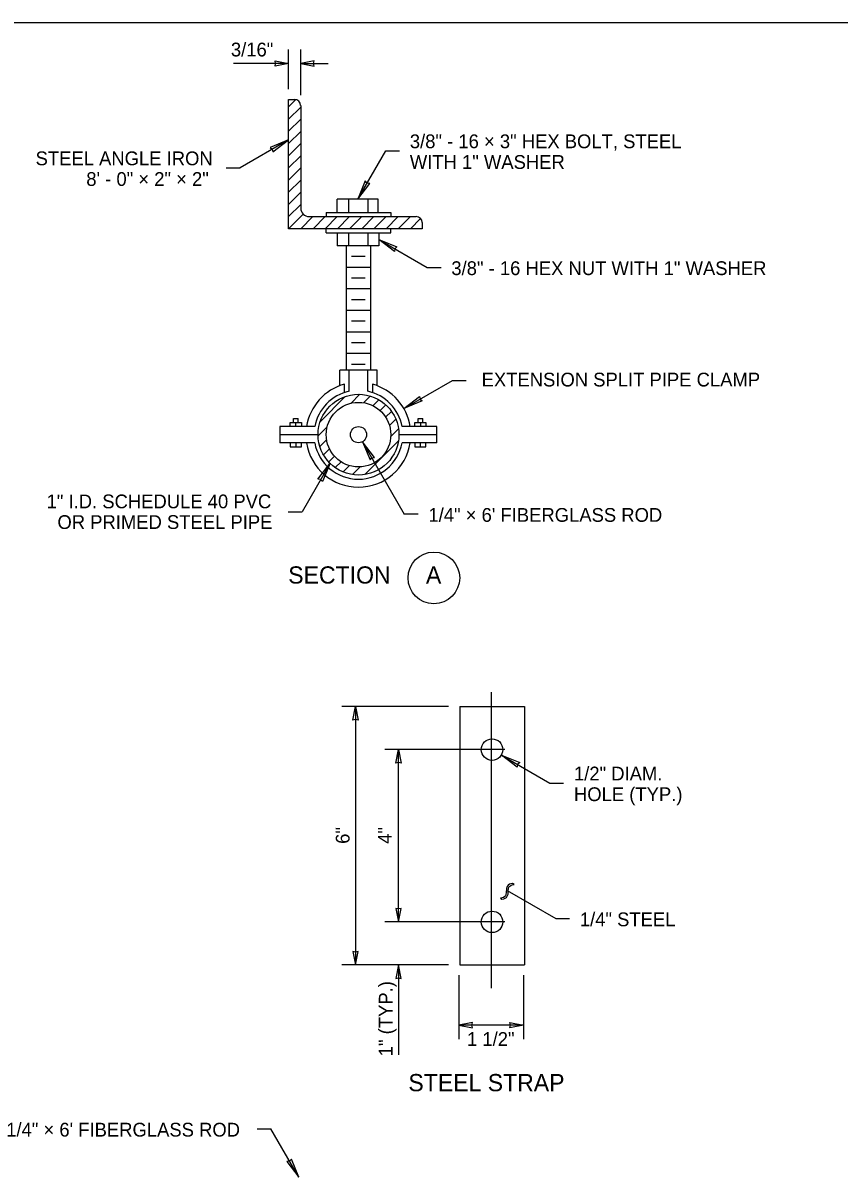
# Model space of a CAD drawing. Extents: x 99862 to 103151, y 100000 to 102076.
# Drawn here: x 100664 to 101611, y 100744 to 102076 of the extents above; entities that cross this region are included whole.
import ezdxf

# ---------------------------------------------------------------- set-up
doc = ezdxf.new("R2010")
doc.units = 0
for name, color, linetype in [('Level 1', 7, 'Continuous'), ('Level 13', 7, 'Continuous'), ('Level 15', 7, 'Continuous'), ('Level 20', 7, 'Continuous'), ('Level 3', 7, 'Continuous'), ('Level 4', 7, 'Continuous'), ('Level 6', 7, 'Continuous'), ('Level 8', 7, 'Continuous'), ('Level 9', 7, 'Continuous')]:
    doc.layers.add(name, color=color, linetype=linetype)

msp = doc.modelspace()

# ---------------------------------------------------------------- linework, layer by layer
at = {"layer": 'Level 1'}
for p, q in [((101223.3, 101232), (101083.8, 101232)), ((101223.3, 101032), (101083.8, 101032))]:
    msp.add_line(p, q, dxfattribs=at)
msp.add_lwpolyline([(99862, 99999.5), (103151, 99999.5), (103151, 102075.5), (99862, 102075.5)], close=True, dxfattribs=at)
at = {"layer": 'Level 13'}
for p, q in [((101028.5, 101855.6), (101028.5, 101870.8)), ((101076.1, 101870.8), (101028.5, 101870.8)), ((101041.7, 101870.8), (101041.7, 101855.4)), ((101063.9, 101870.8), (101063.9, 101855.4)), ((101076.1, 101855.6), (101076.1, 101870.8)), ((101015.6, 101855.4), (101090.6, 101855.4)), ((101015.6, 101855.4), (101015.6, 101850.7)), ((101090.6, 101855.4), (101090.6, 101850.7)), ((101015.6, 101831.9), (101015.6, 101836.6)), ((101015.6, 101831.9), (101090.6, 101831.9)), ((101028.5, 101831.9), (101028.5, 101816.7)), ((101041.7, 101831.9), (101041.7, 101816.7)), ((101063.9, 101831.9), (101063.9, 101816.7)), ((101076.7, 101831.9), (101076.7, 101816.7)), ((101090.6, 101831.9), (101090.6, 101836.6)), ((101076.7, 101816.7), (101028.5, 101816.7)), ((101039, 101816.7), (101039, 101672.5)), ((101067.1, 101816.7), (101067.1, 101672.5)), ((101061.1, 101804.2), (101045, 101804.2)), ((101061.1, 101804.2), (101045, 101804.2)), ((101061.1, 101804.2), (101045, 101804.2)), ((101061.1, 101804.2), (101045, 101804.2)), ((101061.1, 101804.2), (101045, 101804.2)), ((101061.1, 101804.2), (101045, 101804.2)), ((101061.1, 101804.2), (101045, 101804.2)), ((101061.1, 101804.2), (101045, 101804.2)), ((101061.1, 101804.2), (101045, 101804.2)), ((101061.1, 101804.2), (101045, 101804.2)), ((101061.1, 101804.2), (101045, 101804.2)), ((101067.1, 101791.7), (101039, 101791.7)), ((101061.1, 101779.2), (101045, 101779.2)), ((101067.1, 101766.7), (101039, 101766.7)), ((101061.1, 101754.2), (101045, 101754.2)), ((101067.1, 101741.7), (101039, 101741.7)), ((101061.1, 101729.2), (101045, 101729.2)), ((101067.1, 101716.7), (101039, 101716.7)), ((101061.1, 101704.2), (101045, 101704.2)), ((101067.1, 101691.7), (101039, 101691.7)), ((101061.1, 101679.2), (101045, 101679.2)), ((101031.4, 101654.5), (101031.4, 101672.5)), ((101074.7, 101672.5), (101031.4, 101672.5)), ((101042.3, 101647.9), (101042.3, 101672.5)), ((101063.9, 101647.9), (101063.9, 101672.5)), ((101074.7, 101654.5), (101074.7, 101672.5)), ((101036.8, 101646.4), (101036.8, 101656.2)), ((101069.3, 101656.2), (101069.3, 101646.4)), ((100977.9, 101616.3), (100983.2, 101616.3)), ((100977.9, 101611.6), (100977.9, 101616.3)), ((100983.2, 101611.6), (100983.2, 101616.3)), ((101122.6, 101611.6), (101122.6, 101616.3)), ((101122.6, 101616.3), (101127.9, 101616.3)), ((101127.9, 101611.6), (101127.9, 101616.3)), ((100961.8, 101606.9), (100961.8, 101588.1)), ((101002.4, 101606.9), (100961.8, 101606.9)), ((100974, 101606.9), (100974, 101611.6)), ((100980.6, 101606.9), (100980.6, 101611.6)), ((100986.9, 101611.6), (100986.9, 101606.9)), ((101144, 101606.9), (101103.8, 101606.9)), ((101118.6, 101606.9), (101118.6, 101611.6)), ((101125.2, 101611.6), (101125.2, 101606.9)), ((101131.5, 101611.6), (101131.5, 101606.9)), ((101144, 101588.1), (101144, 101606.9)), ((101006.2, 101597.5), (100961.8, 101597.5)), ((101002.4, 101588.1), (100961.8, 101588.1)), ((100974, 101588.1), (100974, 101583.4)), ((100980.6, 101588.1), (100980.6, 101583.4)), ((100986.9, 101583.4), (100986.9, 101588.1)), ((101144, 101597.5), (101100.1, 101597.5)), ((101144, 101588.1), (101103.8, 101588.1)), ((101118.6, 101588.1), (101118.6, 101583.4)), ((101125.2, 101583.4), (101125.2, 101588.1)), ((101131.5, 101583.4), (101131.5, 101588.1))]:
    msp.add_line(p, q, dxfattribs=at)
for points in [[(100974, 101611.6), (100980.6, 101611.6), (100986.9, 101611.6)], [(101118.6, 101611.6), (101125.2, 101611.6), (101131.5, 101611.6)], [(100974, 101583.4), (100980.6, 101583.4), (100986.9, 101583.4)], [(101118.6, 101583.4), (101125.2, 101583.4), (101131.5, 101583.4)]]:
    msp.add_lwpolyline(points, dxfattribs=at)
for radius, start, end in [(60.9, 105.4543, 171.1501), (60.9, 8.8499, 74.5457), (51.6, 102.1192, 169.5243), (51.6, 10.4757, 77.8808), (60.9, 188.8499, 351.1501), (51.6, 190.4757, 349.5243)]:
    msp.add_arc((101053.1, 101597.5), radius, start, end, dxfattribs=at)
at = {"layer": 'Level 15'}
for p, q in [((100972, 101998.6), (100972, 102044.6)), ((100986.1, 101991.6), (100986.1, 102044.6)), ((100972, 102028.6), (100908, 102028.6)), ((100986.1, 102028.6), (101018.1, 102028.6)), ((100972, 101939.8), (100915.7, 101907.3)), ((101052.3, 101870.8), (101084.8, 101927.1)), ((101084.8, 101927.1), (101100.8, 101927.1)), ((100899.7, 101907.3), (100915.7, 101907.3)), ((101076.7, 101824.3), (101133, 101791.8)), ((101133, 101791.8), (101149, 101791.8)), ((101105.9, 101628), (101162.2, 101660.5)), ((101162.2, 101660.5), (101178.2, 101660.5)), ((101057.9, 101589.4), (101106.4, 101505.4)), ((101020.1, 101564.4), (100987.6, 101508.1)), ((100971.6, 101508.1), (100987.6, 101508.1)), ((101122.4, 101505.4), (101106.4, 101505.4)), ((101207.3, 101298.8), (101207.3, 100955)), ((101157.8, 101282), (101033.8, 101282)), ((101049.8, 101282), (101049.8, 100982)), ((101099.8, 101032), (101099.8, 101232)), ((101219.1, 101225.7), (101275.4, 101193.2)), ((101275.4, 101193.2), (101291.4, 101193.2)), ((101225.9, 101068.4), (101282.2, 101035.9)), ((101282.2, 101035.9), (101298.2, 101035.9)), ((101157.8, 100982), (101033.8, 100982)), ((101099.8, 100982), (101099.8, 100877.8)), ((101169.8, 100970), (101169.8, 100896)), ((101244.8, 100970), (101244.8, 100896)), ((100935.5, 100791.7), (100951.5, 100791.7)), ((100984, 100735.5), (100951.5, 100791.7))]:
    msp.add_line(p, q, dxfattribs=at)
for points in [[(100972, 102028.6), (100956.3, 102025.5), (100957, 102028.6), (100956.3, 102031.7)], [(100986.1, 102028.6), (101001.8, 102025.5), (101001.1, 102028.6), (101001.8, 102031.7)], [(100972, 101939.8), (100950.7, 101931), (100953.1, 101928.9), (100953.7, 101925.8)], [(101052.3, 101870.8), (101066.3, 101889.1), (101063.2, 101889.7), (101061.1, 101892.1)], [(101076.7, 101824.3), (101097.9, 101815.5), (101095.5, 101813.4), (101094.9, 101810.3)], [(101105.9, 101628), (101124.1, 101642), (101124.7, 101638.8), (101127.1, 101636.8)], [(101057.9, 101589.4), (101066.7, 101568.2), (101068.8, 101570.6), (101071.9, 101571.2)], [(101020.1, 101564.4), (101011.2, 101543.2), (101009.2, 101545.6), (101006.1, 101546.1)], [(101049.8, 101282), (101052.9, 101266.2), (101049.8, 101267), (101046.7, 101266.2)], [(101099.8, 101232), (101102.9, 101216.2), (101099.8, 101217), (101096.7, 101216.2)], [(101219.1, 101225.7), (101240.4, 101216.9), (101238, 101214.8), (101237.4, 101211.7)], [(101099.8, 101032), (101102.9, 101047.7), (101099.8, 101047), (101096.7, 101047.7)], [(101049.8, 100982), (101052.9, 100997.7), (101049.8, 100997), (101046.7, 100997.7)], [(101099.8, 100982), (101096.7, 100966.2), (101099.8, 100967), (101102.9, 100966.2)], [(100984, 100735.5), (100975.2, 100756.7), (100973.1, 100754.3), (100970, 100753.7)]]:
    msp.add_lwpolyline(points, close=True, dxfattribs=at)
at = {"layer": 'Level 20'}
for p, q in [((101225, 101070.6), (101224.6, 101066.2)), ((101225.9, 101073.2), (101225, 101070.6)), ((101227, 101074.5), (101225.9, 101073.2)), ((101226.8, 101064), (101227.1, 101068.1)), ((101228.4, 101075.6), (101227, 101074.5)), ((101227.1, 101068.1), (101227.3, 101070.6)), ((101227.3, 101070.6), (101227.9, 101072.4)), ((101227.9, 101072.4), (101228.8, 101073.5)), ((101230, 101076.2), (101228.4, 101075.6)), ((101228.8, 101073.5), (101229.9, 101074.3)), ((101229.9, 101074.3), (101231.5, 101074.9)), ((101232, 101076.5), (101230, 101076.2)), ((101231.5, 101074.9), (101233.9, 101075.4)), ((101233.9, 101075.4), (101232, 101076.5)), ((101221.6, 101060.4), (101218, 101059.4)), ((101218, 101059.4), (101219.8, 101058.4)), ((101219.8, 101058.4), (101222, 101058.7)), ((101223, 101061.3), (101221.6, 101060.4)), ((101222, 101058.7), (101223.6, 101059.4)), ((101223.9, 101062.4), (101223, 101061.3)), ((101223.6, 101059.4), (101224.9, 101060.3)), ((101224.4, 101063.8), (101223.9, 101062.4)), ((101224.6, 101066.2), (101224.4, 101063.8)), ((101224.9, 101060.3), (101225.9, 101061.7)), ((101225.9, 101061.7), (101226.8, 101064))]:
    msp.add_line(p, q, dxfattribs=at)
at = {"layer": 'Level 3'}
for p, q in [((101009, 101612.9), (101037.9, 101641.8)), ((101044.2, 101633.9), (101054.6, 101644.4)), ((101059, 101634.6), (101066.8, 101642.4)), ((101069.7, 101631.2), (101076.7, 101638.1)), ((101078.2, 101625.5), (101084.8, 101632.1)), ((101084.7, 101617.8), (101091.4, 101624.6)), ((101089.1, 101608.1), (101096.5, 101615.5)), ((101006.4, 101596.2), (101016.9, 101606.6)), ((101090.6, 101595.4), (101099.5, 101604.4)), ((101008.4, 101584), (101016.3, 101591.8)), ((101060.6, 101551.4), (101099.4, 101590.2)), ((101012.6, 101574.1), (101019.6, 101581.1)), ((101018.7, 101566), (101025.3, 101572.6)), ((101026.2, 101559.4), (101033, 101566.1)), ((101035.3, 101554.3), (101042.6, 101561.7)), ((101046.4, 101551.2), (101055.3, 101560.2))]:
    msp.add_line(p, q, dxfattribs=at)
for radius in [46.9, 37.5]:
    msp.add_circle((101053.2, 101597.6), radius, dxfattribs=at)
at = {"layer": 'Level 4'}
msp.add_line((101244.8, 100912), (101169.8, 100912), dxfattribs=at)
for points in [[(101169.8, 100912), (101185.5, 100908.9), (101184.8, 100912), (101185.5, 100915.1)], [(101244.8, 100912), (101229.1, 100908.9), (101229.8, 100912), (101229.1, 100915.1)]]:
    msp.add_lwpolyline(points, close=True, dxfattribs=at)
at = {"layer": 'Level 6'}
msp.add_circle((101053.2, 101597.6), 9.38, dxfattribs=at)
at = {"layer": 'Level 8'}
for p, q in [((100972, 101836.6), (100972, 101986.6)), ((100972, 101986.6), (100979, 101986.6)), ((100972, 101978), (100980.5, 101986.5)), ((100972, 101963.8), (100986.1, 101977.9)), ((100986.1, 101979.6), (100986.1, 101860.7)), ((100972, 101949.7), (100986.1, 101963.7)), ((100972, 101935.5), (100986.1, 101949.6)), ((100972, 101921.4), (100986.1, 101935.4)), ((100972, 101907.2), (100986.1, 101921.3)), ((100972, 101893.1), (100986.1, 101907.2)), ((100972, 101879), (100986.1, 101893)), ((100972, 101864.8), (100986.1, 101878.9)), ((100972, 101850.7), (100986.1, 101864.7)), ((100972.1, 101836.6), (100989.1, 101853.6)), ((100986.2, 101836.6), (101000.3, 101850.7)), ((100996.1, 101850.7), (101120.1, 101850.7)), ((101000.4, 101836.6), (101014.4, 101850.7)), ((101014.5, 101836.6), (101028.6, 101850.7)), ((101028.7, 101836.6), (101042.7, 101850.7)), ((101042.8, 101836.6), (101056.9, 101850.7)), ((101056.9, 101836.6), (101071, 101850.7)), ((101071.1, 101836.6), (101085.2, 101850.7)), ((101085.2, 101836.6), (101099.3, 101850.7)), ((101099.4, 101836.6), (101113.4, 101850.7)), ((101113.5, 101836.6), (101125.2, 101848.4)), ((101127.1, 101843.7), (101127.1, 101836.6)), ((101127.1, 101836.6), (100972, 101836.6))]:
    msp.add_line(p, q, dxfattribs=at)
for centre, radius, start, end in [((100979, 101979.6), 7.03, 0, 90), ((100996.1, 101860.7), 10, 180, 270), ((101120.1, 101843.7), 7.03, 0, 90), ((101120.1, 101843.7), 7.03, 270, 270.0003)]:
    msp.add_arc(centre, radius, start, end, dxfattribs=at)
at = {"layer": 'Level 9'}
for p, q in [((101170.8, 101282), (101245.8, 101282)), ((101170.8, 101282), (101170.8, 100982)), ((101245.8, 101282), (101245.8, 100982)), ((101170.8, 100982), (101245.8, 100982))]:
    msp.add_line(p, q, dxfattribs=at)
for centre, radius in [((101140.7, 101431.3), 30), ((101208.3, 101232), 12.5), ((101208.3, 101032), 12.5)]:
    msp.add_circle(centre, radius, dxfattribs=at)

# ---------------------------------------------------------------- texts
at = {"layer": 'Level 15'}
for s, p in [('1" I.D. SCHEDULE 40 PVC', (100691, 101512.1)), ('OR PRIMED STEEL PIPE', (100703.6, 101488.1))]:
    msp.add_text(s, height=16, dxfattribs=at).set_placement(p)
at = {"layer": 'Level 20'}
for s, height, p in [('3/16"', 16, (100905, 102036.6)), ('3/8" - 16 × 3" HEX BOLT, STEEL', 16, (101112.8, 101930.1)), ('STEEL ANGLE IRON', 16, (100678.2, 101910.3)), ('WITH 1" WASHER', 16, (101112.8, 101906.1)), ('8\' - 0" × 2" × 2"', 16, (100737.1, 101886.3)), ('3/8" - 16 HEX NUT WITH 1" WASHER', 16, (101161, 101782.8)), ('1/4" × 6\' FIBERGLASS ROD', 16, (101134.4, 101496.4)), ('SECTION', 20, (100971.6, 101424.7)), ('A', 20, (101131.5, 101424.7)), ('1/2" DIAM.', 16, (101303.4, 101196.2)), ('HOLE (TYP.)', 16, (101303.4, 101172.2)), ('1/4" STEEL', 16, (101310.2, 101026.9)), ('1 1/2"', 16, (101179.2, 100888)), ('STEEL STRAP', 20, (101111.1, 100835.4)), ('1/4" × 6\' FIBERGLASS ROD', 16, (100644.1, 100782.8))]:
    msp.add_text(s, height=height, dxfattribs=at).set_placement(p)
for s, rotation, p in [(' EXTENSION SPLIT PIPE CLAMP', 360, (101190.2, 101653.5)), ('6"', 90, (101042.8, 101122.6)), ('4"', 90, (101091.8, 101122.6)), ('1" (TYP.)', 90, (101092.8, 100876))]:
    msp.add_text(s, height=16, rotation=rotation, dxfattribs=at).set_placement(p)

doc.saveas('drawing.dxf')
